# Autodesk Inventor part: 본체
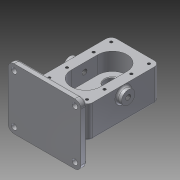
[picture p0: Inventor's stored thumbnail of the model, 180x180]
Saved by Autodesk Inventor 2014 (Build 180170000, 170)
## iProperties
Created: 2020-04
Part Number: 본체
Material: 알루미늄 6061
Document SubType Name: Modeling
Designer: kh
Density: 2.71 g/cm^3
Appearance: 알루미늄 - 평지
Mass: 1477.4 g
Surface Area: 819.403 cm^2
Volume: 545.165 cm^3
Author: kh
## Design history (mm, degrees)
sketch "스케치1"
  geometry: L1 (-40, -60)-(40, -60); L2 (40, -60)-(40, 60); L3 (40, 60)-(-40, 60); L4 (-40, 60)-(-40, -60); L5 (-40, -60)-(40, 60); L6 (40, -60)-(-40, 60); 1 further point
  constraints: 12 end point, 2 midpoint, 2 parallel, 1 horizontal, 1 perpendicular
  dimensions: "d0" = 80 distance of L3.end L2.end; "d1" = 120 distance of L2.end L1.end
extrude "돌출1" new body sketch "스케치1" distance "d2" = 53; taper "d3" = 0 deg
fillet "모깎기1" dims "d4" = 9
sketch "스케치2"
  geometry: L1 (0, 22)-(0, -22); L2 (-24, 22)-(-24, -22); L3 (24, -22)-(24, 22); A1 r 24 centre (0, 22) between (24, 22) and (-24, 22); A2 r 24 centre (0, -22) between (-24, -22) and (24, -22); 2 further points
  constraints: 8 end point, 4 point on circle, 4 tangent, 2 centre point, 2 coincident, 1 midpoint, 1 parallel, 1 vertical
  dimensions: "d5" = 44 distance of L1.start L1.end; "d6" = 48 diameter of A2
extrude "돌출2" cut sketch "스케치2" distance "d7" = 29; taper "d8" = 0 deg
sketch "스케치3"
  geometry: 3 further points
  constraints: 2 vertical alignment
  dimensions: "d9" = 22 distance of point (0, 0) point (0, 22); "d10" = 22 distance of point (0, 0) point (0, -22)
hole "구멍1" sketch "스케치3" at (0, 22), (0, -22) diameter "d11" = 25; stored, may be unused: countersink angle "d15" = 90 deg, drill point angle "d17" = 0 deg; dims "d12" = 6, "d13" = 4, "d14" = 2, "d16" = 15
sketch "스케치4"
  geometry: C1 r 12.5 at (0, 22) reference; C2 r 19 at (0, 22); 1 further point
  constraints: 1 centre point, 1 coincident
  dimensions: "d18" = 38 diameter of C2
extrude "돌출3" join sketch "스케치4" distance "d19" = 17; taper "d20" = 0 deg
hole "구멍2" diameter "d23" = 28; stored, may be unused: countersink angle "d27" = 90 deg, drill point angle "d29" = 0 deg; dims "d21" = 10, "d22" = 10, "d24" = 6, "d25" = 4, "d26" = 2, "d28" = 7.3
hole "구멍3" diameter "d32" = 17; stored, may be unused: countersink angle "d36" = 90 deg, drill point angle "d38" = 0 deg; dims "d30" = 10, "d31" = 10, "d33" = 6, "d34" = 4, "d35" = 2, "d37" = 7.3
chamfer "모따기1" distance "d39" = 0.7; stored, may be unused: second distance "d40" = 2, angle "d41" = 30 deg
fillet "모깎기2" dims "d42" = 0.5
chamfer "모따기2" distance "d43" = 1; stored, may be unused: second distance "d44" = 2, angle "d45" = 30 deg
sketch "스케치5"
  geometry: 9 further points
  constraints: 6 vertical alignment, 4 horizontal alignment
  dimensions: "d46" = 22 vertical distance of point (31, 22) point (0, 0); "d47" = 44 distance of point (31, 22) point (31, -22); "d48" = 29 distance of point (31, 51) point (31, 22); "d49" = 102 distance of point (31, -51) point (31, 51); "d50" = 62 distance of point (31, 51) point (-31, 51); "d51" = 31 horizontal distance of point (0, 0) point (31, -51)
hole "구멍4" sketch "스케치5" at (-31, 51), (31, 51), (31, 22), (31, -22), (31, -51), (-31, -51), (-31, -22), (-31, 22) diameter "d52" = 4.459; stored, may be unused: countersink angle "d56" = 90 deg, drill point angle "d58" = 118 deg; dims "d53" = 10, "d54" = 4, "d55" = 2, "d57" = 12
node "작업 평면1"
sketch "스케치6"
  geometry: L1 (-60, -70)-(60, -70); L2 (60, -70)-(60, 30); L3 (60, 30)-(-60, 30); L4 (-60, 30)-(-60, -70); L5 (-60, -70)-(60, 30); L6 (60, -70)-(-60, 30); L7 (-19, -70)-(19, -70) reference; 3 further points
  constraints: 12 end point, 4 midpoint, 2 parallel, 1 horizontal, 1 perpendicular
  dimensions: "d60" = 120 distance of L3.end L2.end; "d61" = 100 distance of L2.end L1.end
extrude "돌출4" join sketch "스케치6" distance "d62" = 10; taper "d63" = 0 deg
fillet "모깎기3" dims "d64" = 10
sketch "스케치7"
  geometry: L1 (-50, -30)-(50, -30) reference; L2 (60, -20)-(60, 60) reference; 5 further points
  constraints: 2 horizontal alignment, 2 vertical alignment
  dimensions: "d65" = 100 distance of point (50, 60) point (-50, 60); "d66" = 80 distance of point (50, 60) point (50, -20); "d67" = 10 distance from line of L1 point (50, -20); "d68" = 10 distance from line of L2 point (50, -20)
hole "구멍5" sketch "스케치7" at (-50, 60), (-50, -20), (50, -20), (50, 60) diameter "d69" = 9; stored, may be unused: countersink angle "d73" = 90 deg, drill point angle "d75" = 0 deg; dims "d70" = 9, "d71" = 4, "d72" = 2, "d74" = 12
fillet "모깎기4" dims "d76" = 3
sketch "스케치8"
  geometry: L1 (24, 16.5)-(-24, 16.5); L2 (-24, 16.5)-(-24, 36.5); L3 (-24, 36.5)-(24, 36.5); L4 (24, 36.5)-(24, 16.5); L5 (24, 16.5)-(-24, 36.5); L6 (-24, 16.5)-(24, 36.5); L7 (31, 53)-(31, 0) reference; L8 (-31, 53)-(31, 53) reference; L9 (-31, 0)-(-31, 53) reference; L10 (31, 0)-(-31, 0) reference; 6 further points
  constraints: 12 end point, 6 midpoint, 2 parallel, 1 horizontal, 1 horizontal alignment, 1 perpendicular, 1 vertical alignment
  dimensions: "d77" = 48 distance of L2.end L3.end; "d78" = 20 distance of L1.end L2.end
extrude "돌출5" join sketch "스케치8" stored distance "d79" = 10; taper "d80" = 0 deg
sketch "스케치9"
  geometry: L1 (-80, 20)-(-80, -60) reference; L2 (-80, -53)-(-67.182, -45.6); L3 (-80, -53)-(-65.199, -53); L4 (-83, -70)-(-90, -70) reference; 1 further point
  constraints: 4 end point, 1 equal length, 1 horizontal, 1 point on line
  dimensions: "d81" = 30 deg angle of L3 L2; "d82" = 17 distance from line of L4 L2.start
feature "리브1" sketch "스케치9" dims "d83" = 1, "d84" = 48, "d85" = 0, "d86" = 0, "d87" = 1, "d88" = 1
sketch "스케치10"
  geometry: L1 (-80, 20)-(-80, -60) reference; L2 (-80, 0)-(-66.947, -7.536); L3 (-80, 0)-(-64.928, 0); L4 (-80, -53)-(-60, -41.453) reference; 1 further point
  constraints: 4 end point, 1 equal length, 1 horizontal, 1 point on line
  dimensions: "d89" = 30 deg angle of L2 L3; "d90" = 53 distance of L2.start L4.start
feature "리브2" sketch "스케치10" dims "d91" = 1, "d92" = 48, "d93" = 0, "d94" = 0, "d95" = 1, "d96" = 1
sketch "스케치11"
  geometry: L1 (-20.739, -16.998)-(20.739, -16.998); L2 (20.739, -16.998)-(20.739, -23.002); L3 (20.739, -23.002)-(-20.739, -23.002); L4 (-20.739, -23.002)-(-20.739, -16.998); L5 (-20.739, -16.998)-(20.739, -23.002); L6 (20.739, -16.998)-(-20.739, -23.002); L7 (-50, -30)-(50, -30) reference; L8 (-60, 60)-(-60, -20) reference; 2 further points
  constraints: 4 end point, 1 midpoint, 2 other
  dimensions: "d97" = 10 distance from line of L7 point (0, -20); "d98" = 60 distance from line of point (0, -20) L8
feature "엠보싱1" sketch "스케치11" dims "d0" = 80, "d1" = 120, "d99" = 0.5, "d100" = 0
sketch "스케치12"
  geometry: L1 (-20, -39)-(60, -39) reference; C1 r 11 at (14, 51); 2 further points
  constraints: 1 centre point, 1 coincident
  dimensions: "d101" = 14 distance of point (14, 51) point (0, 51); "d102" = 90 distance from line of L1 point (14, 51); "d103" = 22 diameter of C1
extrude "돌출6" join sketch "스케치12" distance "d104" = 8; taper "d105" = 0 deg
sketch "스케치13"
  geometry: C1 r 11 at (-14, 51) reference; C2 r 11 at (-14, 51); 1 further point
  constraints: 1 centre point, 1 coincident
  dimensions: "d106" = 22 diameter of C2
extrude "돌출7" join sketch "스케치13" distance "d107" = 8; taper "d108" = 0 deg
fillet "모깎기5" dims "d118" = 3
fillet "모깎기6" dims "d119" = 3
fillet "모깎기7" dims "d120" = 3
fillet "모깎기8" dims "d121" = 3
fillet "모깎기9" dims "d122" = 3
hole "구멍7" diameter "d125" = 8.376; stored, may be unused: countersink angle "d129" = 90 deg, drill point angle "d131" = 0 deg; dims "d123" = 10, "d124" = 10, "d126" = 9, "d127" = 4, "d128" = 2, "d130" = 12
node "솔리드1"
node "투영된 루프1"
